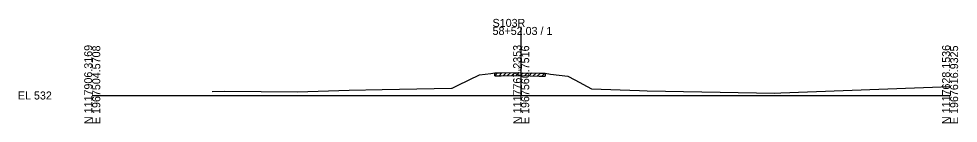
# Model space of a CAD drawing. Extents: x 974 to 1303, y 990 to 10019.
# Drawn here: x 974.3 to 1302.8, y 1490.3 to 1526.8 of the extents above; entities that cross this region are included whole.
import ezdxf

# ---------------------------------------------------------------- set-up
doc = ezdxf.new("R2010")
doc.units = 0
for name, color, linetype in [('Level 10', 7, 'Continuous'), ('Level 60', 7, 'Continuous'), ('Level 61', 7, 'Continuous'), ('Level 63', 7, 'Continuous')]:
    doc.layers.add(name, color=color, linetype=linetype)

msp = doc.modelspace()

# ---------------------------------------------------------------- linework, layer by layer
at = {"layer": 'Level 60'}
for p, q in [((1142.97, 1507.91), (1149.07, 1507.99)), ((1149.07, 1507.99), (1150, 1507.97)), ((1150, 1507.97), (1156.24, 1507.81)), ((1127.99, 1503.63), (1135.37, 1507.21)), ((1135.37, 1507.21), (1139.34, 1507.7)), ((1139.34, 1507.7), (1140.75, 1507.88)), ((1140.75, 1507.88), (1142.97, 1507.91)), ((1156.24, 1507.81), (1158.35, 1507.76)), ((1158.35, 1507.76), (1160.22, 1507.51)), ((1160.22, 1507.51), (1166.31, 1506.7)), ((1166.31, 1506.7), (1168.82, 1505.46)), ((1168.82, 1505.46), (1174.65, 1502.37)), ((1041.89, 1501.4), (1046.32, 1501.49)), ((1046.32, 1501.49), (1071.8, 1501.33)), ((1071.8, 1501.33), (1089.9, 1501.88)), ((1089.9, 1501.88), (1101.37, 1502.1)), ((1101.37, 1502.1), (1125.61, 1502.54)), ((1125.61, 1502.54), (1125.82, 1502.57)), ((1125.82, 1502.57), (1127.99, 1503.63)), ((1174.65, 1502.37), (1191.42, 1501.72)), ((1191.42, 1501.72), (1194.09, 1501.61)), ((1194.09, 1501.61), (1232.26, 1500.94)), ((1240.82, 1500.91), (1300, 1503.1)), ((1232.26, 1500.94), (1238.65, 1500.8)), ((1238.65, 1500.8), (1240.82, 1500.91))]:
    msp.add_line(p, q, dxfattribs=at)
at = {"layer": 'Level 61'}
for p, q in [((1146.75, 1506.96), (1147.77, 1507.97)), ((1148.25, 1506.98), (1149.26, 1507.99)), ((1140.75, 1506.88), (1141.77, 1507.89)), ((1140.75, 1506.88), (1140.75, 1507.88)), ((1140.75, 1506.88), (1142.97, 1506.91)), ((1142.25, 1506.9), (1143.27, 1507.91)), ((1142.97, 1506.91), (1149.07, 1506.99)), ((1143.75, 1506.92), (1144.77, 1507.93)), ((1145.25, 1506.94), (1146.27, 1507.95)), ((1149.07, 1506.99), (1150, 1506.97)), ((1149.75, 1506.98), (1150.73, 1507.95)), ((1150, 1506.97), (1156.24, 1506.81)), ((1151.25, 1506.94), (1152.23, 1507.91)), ((1152.75, 1506.9), (1153.73, 1507.88)), ((1154.25, 1506.86), (1155.23, 1507.84)), ((1155.75, 1506.83), (1156.73, 1507.8)), ((1156.24, 1506.81), (1158.35, 1506.76)), ((1157.25, 1506.79), (1158.23, 1507.76)), ((1158.35, 1507.76), (1158.35, 1506.76)), ((1158.35, 1506.76), (1158.35, 1506.76))]:
    msp.add_line(p, q, dxfattribs=at)
at = {"layer": 'Level 63'}
for p, q in [((1150, 1500), (1150, 1523.98)), ((1000, 1500), (1150, 1500)), ((1150, 1500), (1300, 1500))]:
    msp.add_line(p, q, dxfattribs=at)

# ---------------------------------------------------------------- texts
at = {"layer": 'Level 10'}
msp.add_text('539.97', height=0.9, rotation=90, dxfattribs=at).set_placement((1149.95, 1508.47))
at = {"layer": 'Level 63'}
for s, p in [('S103R', (1140, 1523.98)), ('58+52.03 / 1', (1140, 1521.18)), ('EL 532', (974, 1498.6))]:
    msp.add_text(s, height=2.8, dxfattribs=at).set_placement(p)
for s, p in [('N 1117906.3169', (1000, 1490)), ('E 1967504.5708', (1002.8, 1490)), ('N 1117767.2353', (1150, 1490)), ('E 1967560.7516', (1152.8, 1490)), ('N 1117628.1536', (1300, 1490)), ('E 1967616.9325', (1302.8, 1490))]:
    msp.add_text(s, height=2.8, rotation=90, dxfattribs=at).set_placement(p)

doc.saveas('drawing.dxf')
